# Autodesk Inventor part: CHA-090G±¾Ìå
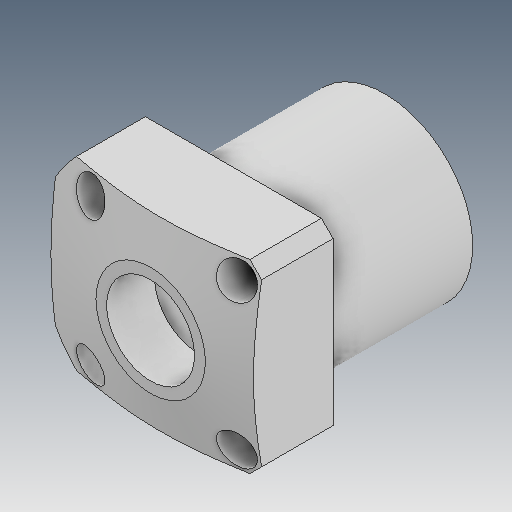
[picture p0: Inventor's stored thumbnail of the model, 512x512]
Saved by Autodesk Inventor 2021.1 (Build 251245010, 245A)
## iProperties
Created: 2019-05
Part Number: CHA-090G±¾Ìå
Material: Ogólny
Document SubType Name: Modeling
Designer: user
Density: 1 g/cm^3
Appearance: Domyślna
Author: user
Revision Number: ÈÎºÎ
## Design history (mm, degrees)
feature "ÊäÈë1"
node "Bryła1"
